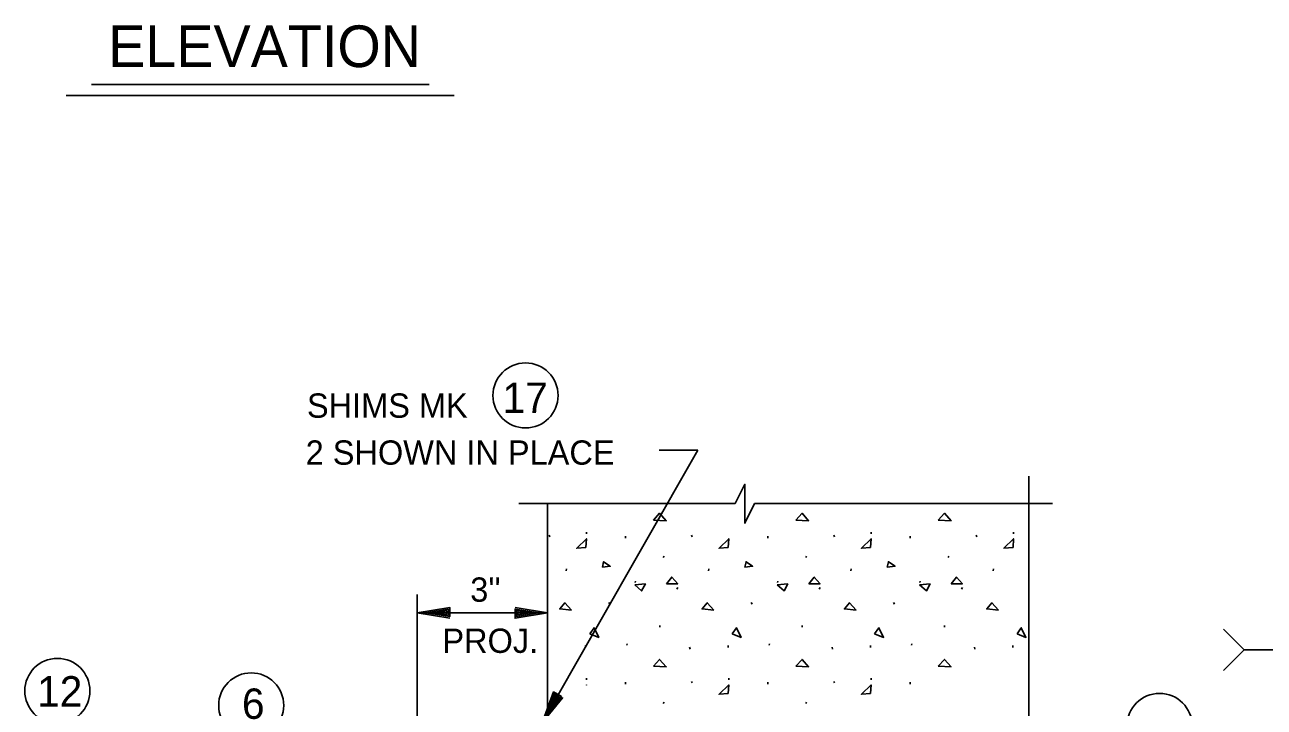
# Model space of a CAD drawing. Extents: x -0.2 to 13.5, y -0.2 to 9.5.
# Drawn here: x 2.53 to 4.91, y 2.607 to 3.918 of the extents above; entities that cross this region are included whole.
import ezdxf

# ---------------------------------------------------------------- set-up
doc = ezdxf.new("R2010")
doc.units = 0
for name, color, linetype in [('Level 10', 7, 'Continuous'), ('Level 13', 7, 'Continuous'), ('Level 2', 7, 'Continuous'), ('Level 3', 7, 'Continuous'), ('Level 4', 7, 'Continuous')]:
    doc.layers.add(name, color=color, linetype=linetype)

msp = doc.modelspace()

# ---------------------------------------------------------------- linework, layer by layer
at = {"layer": 'Level 10'}
for p, q in [((3.5379, 2.9348), (3.5369, 2.9375)), ((3.6083, 2.9403), (3.6083, 2.9438)), ((3.6834, 2.9322), (3.6834, 2.936)), ((3.8113, 2.9348), (3.8102, 2.9375)), ((3.9568, 2.9322), (3.9568, 2.936)), ((4.0846, 2.9348), (4.0835, 2.9375)), ((4.1549, 2.9403), (4.1549, 2.9438)), ((4.2301, 2.9322), (4.2301, 2.936)), ((4.3579, 2.9348), (4.3568, 2.9375)), ((4.4282, 2.9403), (4.4282, 2.9438)), ((3.756, 2.8947), (3.7574, 2.8977)), ((4.0293, 2.8947), (4.0307, 2.8977)), ((4.3026, 2.8947), (4.304, 2.8977)), ((3.5694, 2.8695), (3.57, 2.8732)), ((3.8428, 2.8695), (3.8433, 2.8732)), ((4.1161, 2.8695), (4.1166, 2.8732)), ((4.3894, 2.8695), (4.3899, 2.8732)), ((3.702, 2.8467), (3.7023, 2.8495)), ((3.7818, 2.8342), (3.7837, 2.8373)), ((3.9753, 2.8467), (3.9756, 2.8495)), ((4.0551, 2.8342), (4.057, 2.8373)), ((4.2486, 2.8467), (4.2489, 2.8495)), ((4.3284, 2.8342), (4.3303, 2.8373)), ((3.6531, 2.805), (3.6514, 2.8083)), ((3.9264, 2.805), (3.9247, 2.8083)), ((4.1997, 2.805), (4.198, 2.8083)), ((3.7493, 2.7614), (3.7491, 2.7645)), ((4.0226, 2.7614), (4.0224, 2.7645)), ((4.2959, 2.7614), (4.2957, 2.7645)), ((3.6069, 2.7219), (3.6069, 2.7257)), ((3.6858, 2.7263), (3.6863, 2.7292)), ((3.8075, 2.7189), (3.8064, 2.7227)), ((3.8803, 2.7219), (3.8803, 2.7257)), ((3.9591, 2.7263), (3.9596, 2.7292)), ((4.0808, 2.7189), (4.0798, 2.7227)), ((4.1536, 2.7219), (4.1536, 2.7257)), ((4.2324, 2.7263), (4.2329, 2.7292)), ((4.3541, 2.7189), (4.3531, 2.7227)), ((4.4269, 2.7219), (4.4269, 2.7257)), ((3.6083, 2.6597), (3.6083, 2.6632)), ((3.6834, 2.6517), (3.6834, 2.6554)), ((3.8113, 2.6542), (3.8102, 2.6569)), ((3.8816, 2.6597), (3.8816, 2.6632)), ((3.9568, 2.6517), (3.9568, 2.6554)), ((4.0846, 2.6542), (4.0835, 2.6569)), ((4.1549, 2.6597), (4.1549, 2.6632)), ((4.2301, 2.6517), (4.2301, 2.6554)), ((3.756, 2.6142), (3.7574, 2.6171)), ((4.0293, 2.6142), (4.0307, 2.6171))]:
    msp.add_line(p, q, dxfattribs=at)
for points in [[(3.7371, 2.9669), (3.7489, 2.9798), (3.7617, 2.9655)], [(4.0104, 2.9669), (4.0223, 2.9798), (4.035, 2.9655)], [(4.2837, 2.9669), (4.2956, 2.9798), (4.3083, 2.9655)], [(3.6073, 2.9142), (3.6083, 2.9309), (3.5898, 2.9128)], [(3.8806, 2.9142), (3.8816, 2.9309), (3.8631, 2.9128)], [(4.1539, 2.9142), (4.1549, 2.9309), (4.1364, 2.9128)], [(4.4273, 2.9142), (4.4282, 2.9309), (4.4097, 2.9128)], [(3.639, 2.8761), (3.6542, 2.878), (3.6414, 2.8866)], [(3.9123, 2.8761), (3.9275, 2.878), (3.9148, 2.8866)], [(4.1856, 2.8761), (4.2008, 2.878), (4.1881, 2.8866)], [(3.7622, 2.8441), (3.7723, 2.8574), (3.7836, 2.8446)], [(4.0355, 2.8441), (4.0456, 2.8574), (4.0569, 2.8446)], [(4.3088, 2.8441), (4.3189, 2.8574), (4.3302, 2.8446)], [(3.7011, 2.8427), (3.7144, 2.8308), (3.7215, 2.8441)], [(3.9744, 2.8427), (3.9877, 2.8308), (3.9948, 2.8441)], [(4.2477, 2.8427), (4.261, 2.8308), (4.2681, 2.8441)], [(3.5794, 2.7937), (3.567, 2.808), (3.5571, 2.7962)], [(3.8527, 2.7937), (3.8403, 2.808), (3.8304, 2.7962)], [(4.126, 2.7937), (4.1136, 2.808), (4.1037, 2.7962)], [(4.3993, 2.7937), (4.3869, 2.808), (4.377, 2.7962)], [(3.6151, 2.7482), (3.6321, 2.7415), (3.6231, 2.76)], [(3.8884, 2.7482), (3.9054, 2.7415), (3.8964, 2.76)], [(4.1617, 2.7482), (4.1788, 2.7415), (4.1698, 2.76)], [(4.435, 2.7482), (4.4521, 2.7415), (4.4431, 2.76)], [(3.7371, 2.6863), (3.7489, 2.6992), (3.7617, 2.685)], [(4.0104, 2.6863), (4.0223, 2.6992), (4.035, 2.685)], [(4.2837, 2.6863), (4.2956, 2.6992), (4.3083, 2.685)], [(3.8806, 2.6337), (3.8816, 2.6503), (3.8631, 2.6323)], [(4.1539, 2.6337), (4.1549, 2.6503), (4.1364, 2.6323)]]:
    msp.add_lwpolyline(points, close=True, dxfattribs=at)
for points in [[(3.6083, 2.6503), (3.6077, 2.6498)], [(3.6082, 2.6497), (3.6083, 2.6503)]]:
    msp.add_lwpolyline(points, dxfattribs=at)
at = {"layer": 'Level 13'}
msp.add_lwpolyline([(3.9312, 2.9983), (3.9126, 2.9608), (3.9126, 3.0357), (3.8939, 2.9983)], dxfattribs=at)
at = {"layer": 'Level 2'}
for p, q in [((4.4576, 2.3013), (4.4576, 3.0512)), ((3.4783, 2.9983), (3.8939, 2.9983)), ((3.5336, 0.823), (3.5336, 2.9983)), ((3.9312, 2.9983), (4.5033, 2.9983))]:
    msp.add_line(p, q, dxfattribs=at)
at = {"layer": 'Level 3'}
for p, q in [((2.6585, 3.8031), (3.3068, 3.8031)), ((2.6095, 3.7822), (3.3547, 3.7822)), ((3.5232, 2.5773), (3.8224, 3.1013)), ((3.8224, 3.1013), (3.7477, 3.1013)), ((3.2836, 2.4997), (3.2836, 2.8238)), ((3.2836, 2.7886), (3.5336, 2.7886)), ((3.2836, 2.7886), (3.2836, 2.7886)), ((3.301, 2.7886), (3.301, 2.7886)), ((3.5163, 2.7886), (3.5163, 2.7886)), ((3.5336, 2.7886), (3.5336, 2.7886))]:
    msp.add_line(p, q, dxfattribs=at)
for points in [[(3.346, 2.7783), (3.2836, 2.7886), (3.346, 2.7989), (3.346, 2.7813), (3.301, 2.7886), (3.3433, 2.7956), (3.3433, 2.7843), (3.3176, 2.7886), (3.3406, 2.7923), (3.3406, 2.7876), (3.335, 2.7886)], [(3.4713, 2.7989), (3.5336, 2.7886), (3.4713, 2.7783), (3.4713, 2.7959), (3.5163, 2.7886), (3.474, 2.7816), (3.474, 2.7929), (3.4996, 2.7886), (3.4766, 2.7849), (3.4766, 2.7896), (3.4823, 2.7886)], [(3.5631, 2.6263), (3.5232, 2.5773), (3.5452, 2.6366), (3.5605, 2.6278), (3.5318, 2.5924), (3.5467, 2.6326), (3.5566, 2.627), (3.5401, 2.6068), (3.5483, 2.6286), (3.5524, 2.6263), (3.5487, 2.6219)]]:
    msp.add_lwpolyline(points, dxfattribs=at)
for centre in [(3.4915, 3.2061), (2.5927, 2.6387), (2.9649, 2.6109), (4.7087, 2.5715)]:
    msp.add_circle(centre, 0.0625, dxfattribs=at)
at = {"layer": 'Level 4'}
for p, q in [((4.8712, 2.7176), (4.8314, 2.7574)), ((4.8712, 2.7176), (4.8314, 2.6778)), ((5.2463, 2.7176), (4.8712, 2.7176))]:
    msp.add_line(p, q, dxfattribs=at)

# ---------------------------------------------------------------- texts
at = {"layer": 'Level 3'}
for s, height, p in [('ELEVATION', 0.08, (2.6903, 3.8367)), ('17', 0.05833, (3.4474, 3.1726)), ('SHIMS MK', 0.04667, (3.0719, 3.1633)), ('2 SHOWN IN PLACE', 0.046667, (3.0694, 3.0731)), ("3''", 0.04667, (3.3853, 2.8099)), ('PROJ.', 0.04667, (3.3319, 2.7117)), ('12', 0.05833, (2.5539, 2.6087)), ('6', 0.0583, (2.9471, 2.585))]:
    msp.add_text(s, height=height, dxfattribs=at).set_placement(p)

doc.saveas('drawing.dxf')
